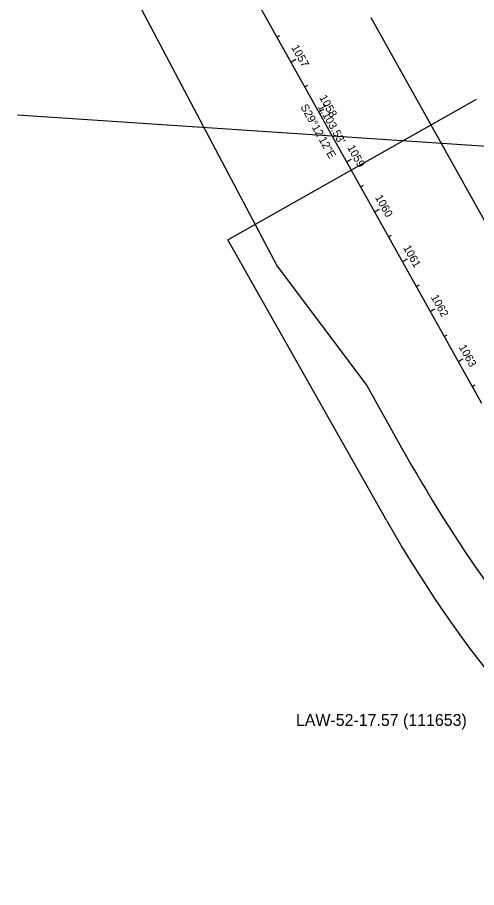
# Model space of a CAD drawing. Extents: x 1947854 to 1951648, y 150068 to 154534.
# Drawn here: x 1947854 to 1948658, y 151523 to 153045 of the extents above; entities that cross this region are included whole.
import ezdxf

# ---------------------------------------------------------------- set-up
doc = ezdxf.new("R2010")
doc.units = 0
for name, color, linetype in [('DR_X_Elev_Flow', 7, 'Continuous'), ('DV_X_Section_VMS_Line', 7, 'Continuous'), ('GE_X_Alignment', 7, 'Continuous'), ('RW_X_Esmt_LA', 7, 'Continuous'), ('SC_Scratch1', 7, 'Continuous'), ('SN_X_Public', 7, 'Continuous'), ('SV_X_Random_Point', 7, 'Continuous')]:
    doc.layers.add(name, color=color, linetype=linetype)

msp = doc.modelspace()

# ---------------------------------------------------------------- linework, layer by layer
at = {"layer": 'DR_X_Elev_Flow'}
msp.add_line((1948479.2, 152705.3), (1948487.9, 152710.1), dxfattribs=at)
at = {"layer": 'DV_X_Section_VMS_Line'}
msp.add_line((1947854.3, 152874.8), (1948955.4, 152801.7), dxfattribs=at)
at = {"layer": 'GE_X_Alignment'}
msp.add_line((1948127.8, 153333.8), (1948666.3, 152370.6), dxfattribs=at)
at = {"layer": 'RW_X_Esmt_LA'}
for p, q in [((1947972, 153246.7), (1948309, 152610.1)), ((1948472.5, 153045.2), (1948805.9, 152448.6)), ((1948309, 152610.1), (1948465.9, 152401.2)), ((1948465.9, 152401.2), (1948526.6, 152292.5))]:
    msp.add_line(p, q, dxfattribs=at)
msp.add_arc((1950889.3, 153613.1), 2706.8, 209.2034, 215.2032, dxfattribs=at)
at = {"layer": 'SC_Scratch1'}
for p, q in [((1948222.6, 152656.3), (1948657.8, 152902.4)), ((1948500.6, 152164.6), (1948222.6, 152656.3))]:
    msp.add_line(p, q, dxfattribs=at)
msp.add_arc((1950328.6, 153198.2), 2100, 209.4864, 232.9007, dxfattribs=at)
at = {"layer": 'SN_X_Public'}
for p, q in [((1948308.4, 153010.8), (1948313.7, 153013.7)), ((1948332.8, 152967.1), (1948341.5, 152972)), ((1948357.2, 152923.5), (1948362.4, 152926.4)), ((1948381.6, 152879.8), (1948390.3, 152884.7)), ((1948406, 152836.2), (1948411.2, 152839.1)), ((1948430.4, 152792.6), (1948439.1, 152797.4)), ((1948454.8, 152748.9), (1948460, 152751.8)), ((1948479.2, 152705.3), (1948487.9, 152710.1)), ((1948503.6, 152661.6), (1948508.8, 152664.6)), ((1948528, 152618), (1948536.7, 152622.9)), ((1948552.4, 152574.3), (1948557.6, 152577.3)), ((1948576.8, 152530.7), (1948585.5, 152535.6)), ((1948601.2, 152487), (1948606.4, 152490)), ((1948625.6, 152443.4), (1948634.3, 152448.3)), ((1948650, 152399.8), (1948655.2, 152402.7))]:
    msp.add_line(p, q, dxfattribs=at)
at = {"layer": 'SV_X_Random_Point'}
for p, q in [((1948332.8, 152967.1), (1948338, 152970.1)), ((1948381.6, 152879.8), (1948386.8, 152882.8)), ((1948430.4, 152792.6), (1948435.6, 152795.5)), ((1948479.2, 152705.3), (1948487.9, 152710.1)), ((1948528, 152618), (1948533.2, 152620.9)), ((1948576.8, 152530.7), (1948582, 152533.6)), ((1948625.6, 152443.4), (1948630.8, 152446.3))]:
    msp.add_line(p, q, dxfattribs=at)

# ---------------------------------------------------------------- texts
at = {"layer": 'DR_X_Elev_Flow'}
for s, p in [('S29°12\'12"E', (1948349.1, 152888.8)), ("1,103.53'", (1948379.7, 152889)), ('1060', (1948479.6, 152730.5))]:
    msp.add_text(s, height=14, rotation=299.2034, dxfattribs=at).set_placement(p)
at = {"layer": 'SC_Scratch1'}
msp.add_text('LAW-52-17.57 (111653)', height=20.833, dxfattribs=at).set_placement((1948341.7, 151806))
at = {"layer": 'SN_X_Public'}
for s, p in [('1057', (1948333.1, 152992.7)), ('1058', (1948382.1, 152905.1)), ('S29°12\'12"E', (1948349.1, 152888.8)), ("1,103.53'", (1948379.7, 152889)), ('1059', (1948430.9, 152817.7)), ('1060', (1948479.6, 152730.5)), ('1061', (1948528.8, 152642.5)), ('1062', (1948577.2, 152555.9)), ('1063', (1948626.1, 152468.6))]:
    msp.add_text(s, height=14, rotation=299.2034, dxfattribs=at).set_placement(p)
at = {"layer": 'SV_X_Random_Point'}
for s, p in [('S29°12\'12"E', (1948349.1, 152888.8)), ("1,103.53'", (1948379.7, 152889)), ('1060', (1948479.6, 152730.5))]:
    msp.add_text(s, height=14, rotation=299.2034, dxfattribs=at).set_placement(p)

doc.saveas('drawing.dxf')
